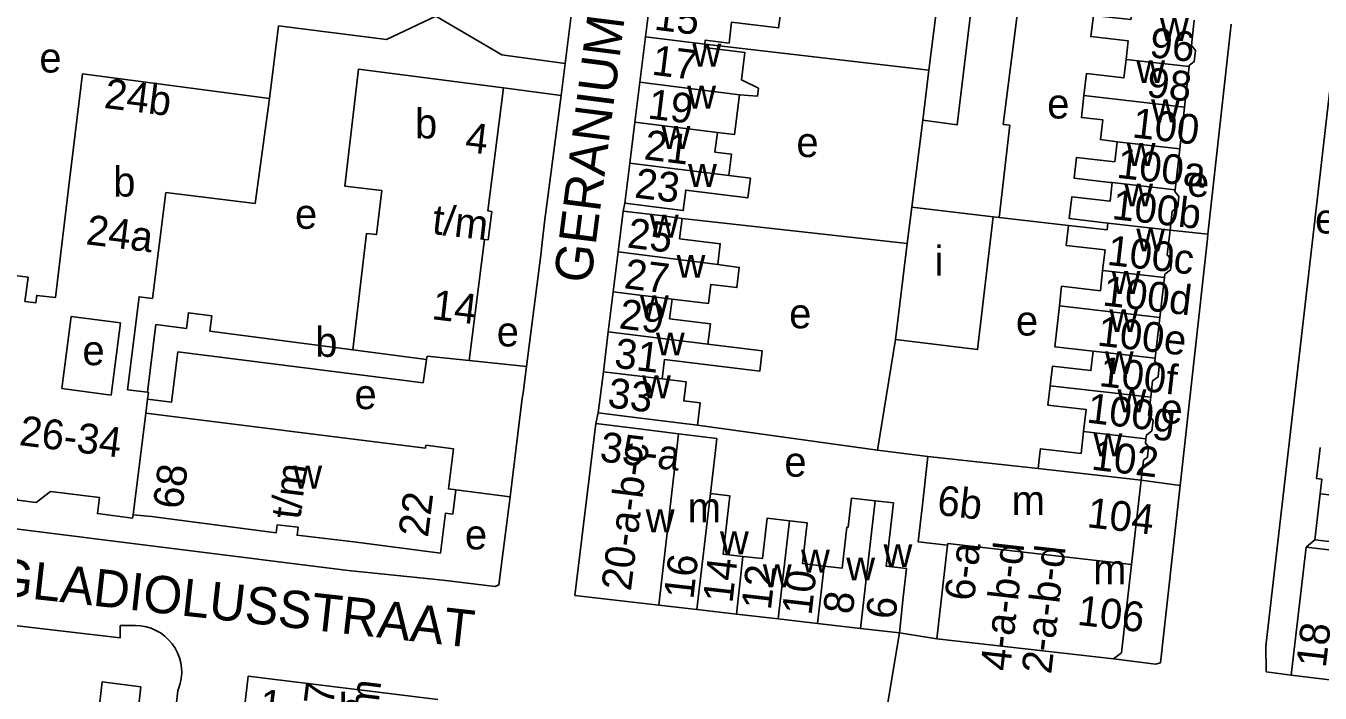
# Model space of a CAD drawing. Extents: x 161258 to 163262, y 380749 to 382054.
# Drawn here: x 162145.4 to 162318.8, y 381217.9 to 381307.3 of the extents above; entities that cross this region are included whole.
import ezdxf

# ---------------------------------------------------------------- set-up
doc = ezdxf.new("R2010")
doc.units = 0
for name, color, linetype in [('BLT_Basislijn', 7, 'Continuous'), ('BLT_Bebouwing', 7, 'Continuous'), ('BLT_Centroide', 7, 'Continuous'), ('BLT_Huisnummer', 7, 'Continuous'), ('BLT_Huisnummer_ tussenligend', 7, 'Continuous'), ('BLT_Huisnummer_reeks', 7, 'Continuous'), ('BLT_Onderverdeling_panden', 7, 'Continuous'), ('BLT_Straatnaam', 7, 'Continuous'), ('BLT_Vlakafsluiter', 7, 'Continuous')]:
    doc.layers.add(name, color=color, linetype=linetype)

msp = doc.modelspace()

# ---------------------------------------------------------------- linework, layer by layer
at = {"layer": 'BLT_Basislijn'}
for p, q in [((162217.69, 381302.26), (162218.96, 381312.68)), ((162178.03, 381297.58), (162179.26, 381307.29)), ((162236.37, 381304.83), (162266.41, 381301.37)), ((162217.69, 381302.26), (162209.83, 381303.32)), ((162209.4, 381298.98), (162217.13, 381297.97)), ((162264.13, 381282.98), (162265.58, 381294.64)), ((162225.46, 381282.47), (162225.65, 381283.52)), ((162215, 381281.74), (162214.55, 381277.87)), ((162233.34, 381281.49), (162263.52, 381278.12)), ((162275.83, 381281.61), (162275.02, 381281.71)), ((162285.13, 381280.55), (162275.83, 381281.61)), ((162298.74, 381279.91), (162303.81, 381279.36)), ((162259.53, 381250.43), (162261.92, 381265.28)), ((162212.5, 381261.64), (162204.81, 381262.43)), ((162222.1, 381255.43), (162221.77, 381254)), ((162235.4, 381253.78), (162259.53, 381250.43)), ((162259.53, 381250.43), (162266.29, 381249.57)), ((162294.86, 381246.4), (162300.1, 381245.7)), ((162203.01, 381245.1), (162210.28, 381244.19)), ((162188.57, 381234.31), (162124.02, 381242.41)), ((162316.96, 381237.44), (162318.13, 381238.41)), ((162188.57, 381234.31), (162201.28, 381233.01)), ((162267.48, 381225.16), (162262.48, 381225.94)), ((162153.79, 381204.11), (162155.64, 381219.4)), ((162155.64, 381219.4), (162160.79, 381218.73)), ((162160.79, 381218.73), (162157.32, 381187.54)), ((162165.76, 381218.18), (162158.03, 381148.74))]:
    msp.add_line(p, q, dxfattribs=at)
for points in [[(162333.77, 381362.06), (162327.65, 381363.04), (162327.49, 381362.81), (162324.77, 381339.11), (162311.57, 381224.14), (162311.63, 381220.74), (162314.97, 381220.26)], [(162275.83, 381281.61), (162277.25, 381293.98), (162276.38, 381294.08), (162278.45, 381310.48)], [(162179.26, 381307.29), (162193.74, 381305.47), (162200.34, 381308.58)], [(162200.34, 381308.58), (162209.17, 381303.41), (162209.83, 381303.32)], [(162303.81, 381279.36), (162306.88, 381307.12), (162306.93, 381307.53)], [(162217.69, 381302.26), (162217.13, 381297.97)], [(162217.13, 381297.97), (162215.03, 381282.02), (162215, 381281.74)], [(162303.81, 381279.36), (162303.74, 381278.77), (162300.1, 381245.7)], [(162214.55, 381277.87), (162214.44, 381276.92), (162212.5, 381261.64)], [(162212.5, 381261.64), (162212.46, 381261.34), (162212.03, 381258.08)], [(162210.28, 381244.19), (162211.93, 381257.39), (162212.03, 381258.08)], [(162300.1, 381245.7), (162297.43, 381221.95), (162296.8, 381221.74), (162291.16, 381222.45)], [(162201.28, 381233.01), (162208.29, 381232.18), (162208.8, 381232.39), (162210.28, 381244.19)], [(162159.39, 381226.92), (162158.05, 381226.93), (162158.05, 381225.29), (162126.58, 381228.93), (162126.76, 381230.93), (162107.32, 381233.47)], [(162159.39, 381226.92), (162160.1, 381226.95), (162160.8, 381226.9), (162161.5, 381226.77), (162162.18, 381226.57), (162162.83, 381226.28), (162163.44, 381225.93), (162164.01, 381225.51), (162164.53, 381225.03), (162164.99, 381224.49), (162165.39, 381223.91), (162165.72, 381223.28), (162165.97, 381222.62), (162166.15, 381221.94), (162166.26, 381221.24), (162166.28, 381220.53), (162166.22, 381219.83), (162166.09, 381219.14), (162165.87, 381218.46), (162165.76, 381218.18)]]:
    msp.add_lwpolyline(points, dxfattribs=at)
at = {"layer": 'BLT_Bebouwing'}
for p, q in [((162266.41, 381301.37), (162269.23, 381324.02)), ((162229.16, 381311.71), (162228.43, 381305.82)), ((162228.43, 381305.82), (162227.67, 381299.73)), ((162265.58, 381294.64), (162266.41, 381301.37)), ((162300.67, 381296.42), (162301.29, 381301.84)), ((162227.67, 381299.73), (162227.01, 381294.39)), ((162300.02, 381290.8), (162300.67, 381296.42)), ((162227.01, 381294.39), (162226.32, 381288.9)), ((162299.4, 381285.33), (162300.02, 381290.8)), ((162226.32, 381288.9), (162225.65, 381283.52)), ((162207.85, 381282.43), (162207.36, 381278.6)), ((162225.46, 381282.47), (162224.78, 381276.99)), ((162264.13, 381282.98), (162263.52, 381278.12)), ((162275.02, 381281.71), (162264.13, 381282.98)), ((162224.78, 381276.99), (162224.12, 381271.63)), ((162263.52, 381278.12), (162261.92, 381265.28)), ((162298, 381273.58), (162297.38, 381268.22)), ((162224.12, 381271.63), (162223.45, 381266.3)), ((162150.21, 381258.68), (162151.45, 381268.35)), ((162151.45, 381268.35), (162158.09, 381267.48)), ((162170.32, 381268.45), (162170.06, 381266.37)), ((162297.38, 381268.22), (162296.74, 381262.75)), ((162156.85, 381257.82), (162158.09, 381267.48)), ((162189.23, 381263.88), (162170.06, 381266.37)), ((162223.45, 381266.3), (162222.79, 381260.95)), ((162165.76, 381263.6), (162198.66, 381259.47)), ((162199.1, 381262.6), (162199.16, 381263.05)), ((162198.66, 381259.47), (162199.1, 381262.6)), ((162150.21, 381258.68), (162156.85, 381257.82)), ((162266.29, 381249.57), (162281.06, 381247.97)), ((162294.86, 381246.4), (162293.57, 381235.1)), ((162318.84, 381244.56), (162318.13, 381238.41)), ((162159.7, 381241.33), (162159.76, 381241.76)), ((162189.34, 381238.13), (162200.95, 381236.61)), ((162314.97, 381220.26), (162316.96, 381237.44)), ((162230.22, 381229.67), (162235.32, 381229.08)), ((162235.32, 381229.08), (162240.65, 381228.46)), ((162240.65, 381228.46), (162246.21, 381227.82)), ((162246.21, 381227.82), (162251.48, 381227.21)), ((162251.48, 381227.21), (162257.26, 381226.54)), ((162257.26, 381226.54), (162262.48, 381225.94)), ((162291.16, 381222.45), (162267.48, 381225.16)), ((162320.51, 381219.61), (162314.97, 381220.26))]:
    msp.add_line(p, q, dxfattribs=at)
for points in [[(162276.83, 381351.74), (162276.19, 381346.8), (162274.79, 381335.93), (162272.81, 381320.01), (162273.33, 381319.95), (162270.2, 381294.03), (162265.58, 381294.64)], [(162236.37, 381304.83), (162236.45, 381305.38), (162239.63, 381304.98), (162239.98, 381307.8), (162246.28, 381307.02), (162246.6, 381309.54), (162242.53, 381310.05)], [(162292.83, 381302.81), (162293.11, 381305.3), (162288.11, 381305.87), (162288.45, 381308.7), (162293.49, 381308.13), (162293.61, 381309.04)], [(162301.29, 381301.84), (162301.3, 381301.99), (162301.95, 381302.51), (162302.12, 381303.99), (162301.59, 381304.66), (162301.98, 381308.08)], [(162241.03, 381298.07), (162243.44, 381297.87), (162243.57, 381298.94), (162241.28, 381300.08), (162241.73, 381303.73), (162236.35, 381304.39), (162236.37, 381304.83)], [(162287.19, 381297.97), (162287.52, 381300.9), (162292.55, 381300.32), (162292.83, 381302.81)], [(162189.99, 381301.48), (162188.14, 381285.83), (162193.1, 381285.24), (162192.4, 381279.33), (162191.07, 381279.49), (162189.23, 381263.88)], [(162209.4, 381298.98), (162189.99, 381301.48)], [(162151.3, 381286.98), (162153.01, 381300.88), (162178.03, 381297.58)], [(162178.03, 381297.58), (162176.12, 381283.5), (162164.14, 381284.98)], [(162209.4, 381298.98), (162207.33, 381282.5), (162207.85, 381282.43)], [(162238.07, 381293.01), (162240.36, 381292.72), (162241.03, 381298.07)], [(162291.64, 381291.76), (162289.41, 381292.06), (162289.71, 381294.71), (162286.85, 381295.03), (162287.19, 381297.97)], [(162239.59, 381287.25), (162239.95, 381290.11), (162237.73, 381290.39), (162238.07, 381293.01)], [(162290.98, 381286.29), (162290.67, 381286.32), (162285.88, 381286.87), (162286.2, 381289.66), (162291.33, 381289.08), (162291.64, 381291.76)], [(162225.65, 381283.52), (162230.62, 381282.9), (162233.5, 381282.55), (162233.84, 381285.28), (162242.17, 381284.25), (162242.5, 381286.89), (162239.59, 381287.25)], [(162145.44, 381271.6), (162145.28, 381270.36), (162146.74, 381270.18), (162146.87, 381271.18), (162149.35, 381270.87), (162151.3, 381286.98)], [(162290.39, 381280.87), (162285.23, 381281.46), (162285.56, 381284.38), (162290.69, 381283.79), (162290.98, 381286.29)], [(162164.14, 381284.98), (162162.37, 381270.76), (162160.58, 381270.99), (162159.03, 381258.52), (162161.68, 381258.19)], [(162298.74, 381279.91), (162299.03, 381282.45), (162299.76, 381283.03), (162299.92, 381284.41), (162299.37, 381285.1), (162299.4, 381285.33)], [(162233.34, 381281.49), (162230.43, 381281.86), (162225.46, 381282.47)], [(162233.34, 381281.49), (162233, 381278.77), (162238.46, 381278.09), (162238.11, 381275.33)], [(162261.92, 381265.28), (162272.94, 381263.9), (162275.02, 381281.71)], [(162289.7, 381274.53), (162290.02, 381277.26), (162284.82, 381277.85), (162285.13, 381280.55)], [(162285.13, 381280.55), (162290.3, 381279.96), (162290.39, 381280.87)], [(162207.36, 381278.6), (162206.84, 381278.67), (162204.81, 381262.43)], [(162298.74, 381279.91), (162298.36, 381276.63), (162298.95, 381275.88), (162298.8, 381274.59), (162298.05, 381274), (162298, 381273.58)], [(162132.25, 381275.28), (162145.69, 381273.61), (162145.44, 381271.6)], [(162238.11, 381275.33), (162241.01, 381274.92), (162240.68, 381272.21), (162237.18, 381272.64), (162236.86, 381270.08), (162231.99, 381270.65)], [(162283.9, 381269.77), (162284.2, 381272.39), (162289.39, 381271.8), (162289.7, 381274.53)], [(162148.7, 381244.9), (162146.77, 381243.4), (162144.31, 381243.72), (162143.22, 381245.13), (162136.38, 381245.99), (162136.89, 381250), (162139.31, 381269.56), (162131.64, 381270.55)], [(162231.99, 381270.65), (162231.67, 381268.05), (162237.13, 381267.37), (162236.79, 381264.64)], [(162161.68, 381258.19), (162162.81, 381267.27), (162166.93, 381266.75), (162167.19, 381268.84), (162170.32, 381268.45)], [(162288.43, 381263.71), (162283.27, 381264.3), (162283.9, 381269.77)], [(162236.79, 381264.64), (162244.09, 381263.74), (162243.75, 381261.01), (162236.45, 381261.92), (162230.99, 381262.59), (162230.67, 381259.97)], [(162165.76, 381263.6), (162164.9, 381256.86), (162161.71, 381257.26)], [(162204.81, 381262.43), (162199.16, 381263.05)], [(162282.67, 381259.07), (162282.97, 381261.68), (162288.13, 381261.09), (162288.43, 381263.71)], [(162296.74, 381262.75), (162296.7, 381262.37), (162297.28, 381261.64), (162297.12, 381260.27), (162296.39, 381259.7), (162296.14, 381257.53)], [(162222.79, 381260.95), (162222.1, 381255.43)], [(162230.67, 381259.97), (162233.87, 381259.57), (162233.56, 381257.04), (162235.78, 381256.76), (162235.4, 381253.78)], [(162287.15, 381252.94), (162287.51, 381255.88), (162282.37, 381256.47), (162282.67, 381259.07)], [(162161.71, 381257.26), (162161.49, 381255.38)], [(162296.14, 381257.53), (162295.86, 381255.15), (162296.45, 381254.42), (162296.28, 381253.02), (162295.56, 381252.45), (162295.5, 381251.93)], [(162161.49, 381255.38), (162198.95, 381250.69), (162199, 381251.09), (162202.7, 381250.62)], [(162222.1, 381255.43), (162227.06, 381254.82), (162235.4, 381253.78)], [(162221.77, 381254), (162218.98, 381230.96), (162230.22, 381229.67)], [(162232.86, 381252.62), (162226.87, 381253.36), (162221.77, 381254)], [(162237.14, 381244.6), (162237.77, 381250), (162238, 381251.98), (162232.86, 381252.62)], [(162281.06, 381247.97), (162281.29, 381250), (162281.36, 381250.62), (162286.8, 381250), (162287.15, 381252.94)], [(162295.5, 381251.93), (162295.44, 381251.39), (162295.86, 381250.86), (162295.76, 381250), (162295.7, 381249.51), (162295.17, 381249.08), (162294.86, 381246.4)], [(162318.85, 381250.78), (162318.75, 381250), (162318.36, 381246.62), (162319.06, 381246.54), (162318.84, 381244.56)], [(162203.01, 381245.1), (162202.02, 381245.24), (162202.7, 381250.62)], [(162268.91, 381237.69), (162264.98, 381238.14), (162265.55, 381243.11), (162266.29, 381249.57)], [(162159.7, 381241.33), (162154.99, 381241.94), (162155.26, 381244.07), (162148.7, 381244.9)], [(162200.95, 381236.61), (162201.62, 381241.98), (162202.61, 381241.86), (162203.01, 381245.1)], [(162241.48, 381236.19), (162238.86, 381236.49), (162239.75, 381244.3), (162237.14, 381244.6)], [(162259.23, 381243.63), (162256.02, 381243.99), (162255.58, 381240.11), (162255.43, 381240.13), (162254.8, 381234.62), (162252.36, 381234.9)], [(162262.48, 381225.94), (162262.98, 381230.74), (162263.42, 381234.57), (162260.69, 381234.88), (162261.66, 381243.35), (162259.23, 381243.63)], [(162159.76, 381241.76), (162162.22, 381241.54), (162178.95, 381239.37), (162179.08, 381240.43), (162181.88, 381240.09), (162181.75, 381239.02), (162189.34, 381238.13)], [(162247.72, 381240.97), (162244.73, 381241.31), (162244.11, 381235.89), (162241.48, 381236.19)], [(162252.36, 381234.9), (162249.46, 381235.23), (162250.08, 381240.7), (162247.72, 381240.97)], [(162267.48, 381225.16), (162268.91, 381237.69)], [(162316.96, 381237.44), (162321.93, 381236.86), (162322.46, 381236.8)], [(162318.13, 381238.41), (162326.58, 381237.44), (162326.63, 381237.81), (162330.58, 381237.35)], [(162293.57, 381235.1), (162292.22, 381223.29), (162291.16, 381222.45)], [(162200.59, 381217.01), (162175.21, 381220.14), (162174.36, 381212.75)]]:
    msp.add_lwpolyline(points, dxfattribs=at)
at = {"layer": 'BLT_Onderverdeling_panden'}
for p, q in [((162236.37, 381304.83), (162228.43, 381305.82)), ((162292.83, 381302.81), (162301.29, 381301.84)), ((162241.03, 381298.07), (162227.67, 381299.73)), ((162287.19, 381297.97), (162300.67, 381296.42)), ((162238.07, 381293.01), (162227.01, 381294.39)), ((162291.64, 381291.76), (162300.02, 381290.8)), ((162239.59, 381287.25), (162226.32, 381288.9)), ((162290.98, 381286.29), (162299.4, 381285.33)), ((162290.39, 381280.87), (162298.74, 381279.91)), ((162238.11, 381275.33), (162224.78, 381276.99)), ((162289.7, 381274.53), (162298, 381273.58)), ((162231.99, 381270.65), (162224.12, 381271.63)), ((162283.9, 381269.77), (162297.38, 381268.22)), ((162236.79, 381264.64), (162223.45, 381266.3)), ((162199.1, 381262.6), (162189.23, 381263.88)), ((162288.43, 381263.71), (162296.74, 381262.75)), ((162230.67, 381259.97), (162222.79, 381260.95)), ((162282.67, 381259.07), (162296.14, 381257.53)), ((162161.49, 381255.38), (162159.76, 381241.76)), ((162232.86, 381252.62), (162232.41, 381248.66)), ((162287.15, 381252.94), (162295.5, 381251.93)), ((162232.41, 381248.66), (162230.22, 381229.67)), ((162281.06, 381247.97), (162294.86, 381246.4)), ((162237.14, 381244.6), (162235.32, 381229.08)), ((162327.31, 381243.64), (162318.84, 381244.56)), ((162259.23, 381243.63), (162257.26, 381226.54)), ((162247.72, 381240.97), (162246.21, 381227.82)), ((162241.48, 381236.19), (162240.65, 381228.46)), ((162252.36, 381234.9), (162251.48, 381227.21))]:
    msp.add_line(p, q, dxfattribs=at)
for points in [[(162161.71, 381257.26), (162161.83, 381258.18), (162161.68, 381258.19)], [(162268.91, 381237.69), (162268.94, 381237.91), (162293.57, 381235.1)]]:
    msp.add_lwpolyline(points, dxfattribs=at)
at = {"layer": 'BLT_Vlakafsluiter'}
msp.add_line((162259.83, 381210.28), (162262.48, 381225.94), dxfattribs=at)

# ---------------------------------------------------------------- texts
at = {"layer": 'BLT_Centroide'}
for s, p in [('w', (162297.38, 381305.28)), ('w', (162234.72, 381301.84)), ('e', (162147.21, 381301.04)), ('w', (162294.2, 381299.62)), ('w', (162234.02, 381296.22)), ('e', (162282.27, 381294.88)), ('b', (162197.55, 381292.22)), ('w', (162296.19, 381294.38)), ('w', (162230.59, 381290.81)), ('e', (162248.66, 381289.71)), ('w', (162292.92, 381288.53)), ('b', (162157.11, 381284.42)), ('w', (162234.14, 381285.72)), ('e', (162301.01, 381284.38)), ('w', (162292.59, 381283.09)), ('e', (162181.47, 381280.1)), ('w', (162229.02, 381278.91)), ('e', (162318.16, 381279.47)), ('w', (162294.2, 381277.06)), ('i', (162267.18, 381273.81)), ('w', (162232.6, 381273.53)), ('w', (162290.91, 381271.38)), ('w', (162227.69, 381268.12)), ('e', (162247.69, 381266.76)), ('e', (162278.07, 381265.79)), ('w', (162290.58, 381266.25)), ('b', (162184.18, 381262.94)), ('e', (162208.5, 381264.33)), ('e', (162152.98, 381261.82)), ('w', (162229.83, 381263.12)), ('w', (162290, 381260.62)), ('w', (162227.97, 381257.38)), ('e', (162189.44, 381255.93)), ('w', (162291.69, 381255.5)), ('e', (162297.45, 381253.99)), ('w', (162288.48, 381249.62)), ('e', (162247.05, 381246.88)), ('w', (162181.23, 381245.28)), ('m', (162234.09, 381240.75)), ('m', (162277.51, 381241.72)), ('w', (162228.47, 381239.41)), ('e', (162204.24, 381237.13)), ('w', (162238.41, 381236.48)), ('w', (162249.28, 381234.03)), ('w', (162260.33, 381234.75)), ('w', (162244.16, 381232.06)), ('w', (162255.34, 381232.97)), ('m', (162288.43, 381232.47)), ('b', (162187.32, 381213.85))]:
    msp.add_text(s, height=4, dxfattribs=at).set_placement(p)
at = {"layer": 'BLT_Huisnummer'}
for s, rotation, p in [('96', 353.4829, (162295.87, 381303.12)), ('17', 352.9032, (162229.16, 381300.77)), ('100', 353.4742, (162293.54, 381292.36)), ('21', 352.9062, (162228.12, 381289.43)), ('100a', 353.4731, (162291.47, 381286.95)), ('100b', 353.4726, (162290.83, 381281.42)), ('25', 352.8956, (162225.87, 381277.61)), ('100c', 353.4649, (162290.18, 381275.28)), ('100d', 353.4803, (162289.57, 381269.84)), ('29', 352.9006, (162224.77, 381266.77)), ('100e', 353.4777, (162288.87, 381264.46)), ('100f', 353.4773, (162289.11, 381259.03)), ('33', 353.0537, (162223.24, 381256.19)), ('100g', 353.1234, (162287.45, 381254.14)), ('102', 353.1251, (162288.07, 381247.84)), ('14', 83.4642, (162240.08, 381229.84)), ('10', 83.4548, (162250.68, 381228.21)), ('6', 83.4758, (162261.92, 381227.64)), ('18', 83.375, (162319.59, 381221.17))]:
    msp.add_text(s, height=4, rotation=rotation, dxfattribs=at).set_placement(p)
at = {"layer": 'BLT_Huisnummer_ tussenligend'}
for s, rotation, p in [('15', 352.907, (162229.49, 381306.8)), ('98', 353.4829, (162295.47, 381297.8)), ('19', 352.9032, (162228.62, 381294.9)), ('23', 352.9062, (162226.85, 381284.3)), ('27', 352.8956, (162225.45, 381272.15)), ('31', 352.9006, (162224.13, 381261.52)), ('16', 83.4657, (162234.84, 381230.35)), ('12', 83.4548, (162245.23, 381228.91)), ('8', 83.4758, (162256.19, 381228.33))]:
    msp.add_text(s, height=4, rotation=rotation, dxfattribs=at).set_placement(p)
at = {"layer": 'BLT_Huisnummer_reeks'}
for s, rotation, p in [('24b', 352.9168, (162155.77, 381296.31)), ('4', 353.2687, (162204.15, 381290.42)), ('24a', 352.9168, (162153.33, 381278.04)), ('t/m', 353.2687, (162199.73, 381279.43)), ('14', 353.2687, (162199.68, 381268)), ('26-34', 352.9096, (162144.39, 381251.12)), ('35-a', 353.0537, (162222.2, 381248.95)), ('20-a-b-c', 82.9076, (162226.47, 381231.45)), ('68', 82.9145, (162166.38, 381242.41)), ('t/m', 82.9249, (162182.17, 381241.04)), ('6b', 353.486, (162267.4, 381241.78)), ('22', 83.0196, (162199.28, 381238.65)), ('104', 353.486, (162287.48, 381240.12)), ('6-a', 83.4758, (162272.46, 381230.11)), ('4-a-b-d', 83.4758, (162277.26, 381220.72)), ('2-a-b-d', 83.4797, (162282.8, 381220.33)), ('106', 353.4785, (162286.18, 381227.03)), ('1', 352.9762, (162176.52, 381214.49)), ('57', 82.9597, (162186.22, 381213.16)), ('t/m', 82.9597, (162192.13, 381212.07))]:
    msp.add_text(s, height=4, rotation=rotation, dxfattribs=at).set_placement(p)
at = {"layer": 'BLT_Straatnaam'}
for s, rotation, p in [('GERANIUMSTRAAT', 82.7202, (162221.09, 381272.66)), ('GLADIOLUSSTRAAT', 353.6443, (162140.97, 381231.09))]:
    msp.add_text(s, height=5, rotation=rotation, dxfattribs=at).set_placement(p)

doc.saveas('drawing.dxf')
